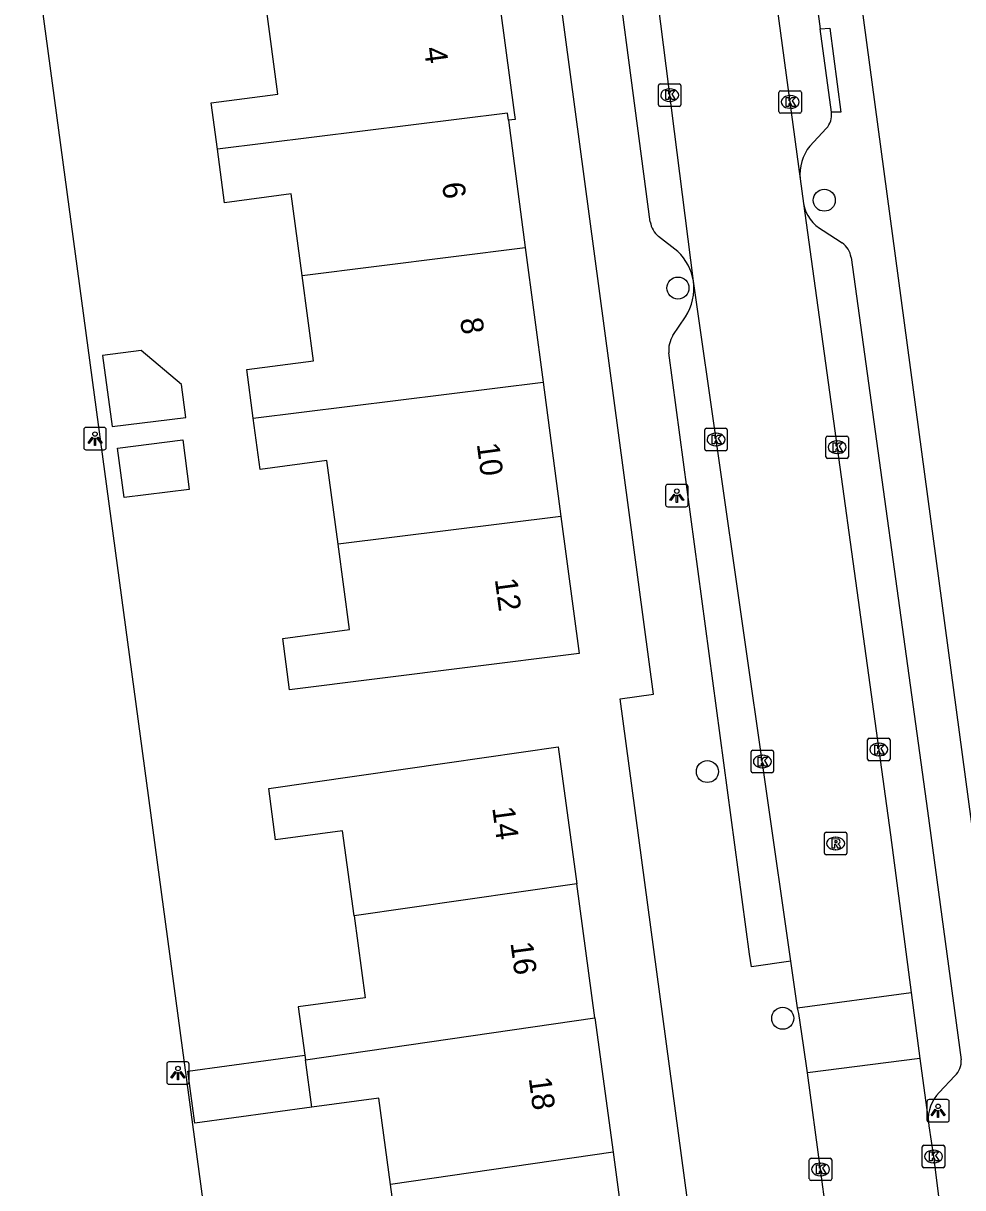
# Model space of a CAD drawing. Extents: x 163427 to 164190, y 380331 to 381641.
# Drawn here: x 163513.3 to 163555.1, y 381440.5 to 381492.3 of the extents above; entities that cross this region are included whole.
import ezdxf

# ---------------------------------------------------------------- set-up
doc = ezdxf.new("R2010")
doc.units = 0
for name, color, linetype in [('IMGEO_Boom', 7, 'Continuous'), ('IMGEO_Kolk', 7, 'Continuous'), ('IMGEO_Lichtpunt', 7, 'Continuous'), ('IMGEO_Pand', 7, 'Continuous'), ('IMGEO_Pand_nummerreeks', 7, 'Continuous'), ('IMGEO_Rijbaan_lokaal_open', 7, 'Continuous'), ('IMGEO_Rioolput', 7, 'Continuous'), ('IMGEO_Voetpad_open', 7, 'Continuous')]:
    doc.layers.add(name, color=color, linetype=linetype)

msp = doc.modelspace()

# ---------------------------------------------------------------- linework, layer by layer
at = {"layer": 'IMGEO_Boom'}
for centre in [(163548.902, 381484.415), (163542.391, 381480.505), (163543.702, 381458.979), (163547.053, 381447.995)]:
    msp.add_circle(centre, 0.489, dxfattribs=at)
at = {"layer": 'IMGEO_Kolk'}
for p, q in [((163541.6, 381489.594), (163542.452, 381489.594)), ((163541.525, 381488.668), (163541.525, 381489.52)), ((163542.013, 381489.374), (163542.038, 381489.374)), ((163542.526, 381489.52), (163542.526, 381488.668)), ((163546.887, 381488.365), (163546.887, 381489.217)), ((163546.962, 381489.291), (163547.814, 381489.291)), ((163547.375, 381489.071), (163547.4, 381489.071)), ((163547.888, 381489.217), (163547.888, 381488.365)), ((163542.452, 381488.594), (163541.6, 381488.594)), ((163542.036, 381488.814), (163542.011, 381488.814)), ((163547.814, 381488.291), (163546.962, 381488.291)), ((163547.398, 381488.511), (163547.373, 381488.511)), ((163543.587, 381473.337), (163543.587, 381474.189)), ((163543.662, 381474.263), (163544.514, 381474.263)), ((163544.075, 381474.043), (163544.1, 381474.043)), ((163544.588, 381474.189), (163544.588, 381473.337)), ((163548.975, 381472.992), (163548.975, 381473.844)), ((163549.05, 381473.918), (163549.902, 381473.918)), ((163549.463, 381473.698), (163549.488, 381473.698)), ((163549.976, 381473.844), (163549.976, 381472.992)), ((163544.514, 381473.263), (163543.662, 381473.263)), ((163544.098, 381473.483), (163544.073, 381473.483)), ((163549.486, 381473.138), (163549.461, 381473.138)), ((163549.902, 381472.918), (163549.05, 381472.918)), ((163550.827, 381459.533), (163550.827, 381460.385)), ((163550.902, 381460.459), (163551.754, 381460.459)), ((163551.315, 381460.239), (163551.34, 381460.239)), ((163551.828, 381460.385), (163551.828, 381459.533)), ((163545.648, 381459), (163545.648, 381459.852)), ((163545.723, 381459.926), (163546.575, 381459.926)), ((163546.136, 381459.706), (163546.161, 381459.706)), ((163546.649, 381459.852), (163546.649, 381459)), ((163551.338, 381459.679), (163551.313, 381459.679)), ((163546.159, 381459.146), (163546.134, 381459.146)), ((163551.754, 381459.459), (163550.902, 381459.459)), ((163546.575, 381458.926), (163545.723, 381458.926)), ((163553.265, 381441.417), (163553.265, 381442.269)), ((163553.34, 381442.343), (163554.192, 381442.343)), ((163553.753, 381442.123), (163553.778, 381442.123)), ((163554.266, 381442.269), (163554.266, 381441.417)), ((163548.238, 381440.841), (163548.238, 381441.693)), ((163548.313, 381441.767), (163549.165, 381441.767)), ((163548.726, 381441.547), (163548.751, 381441.547)), ((163549.239, 381441.693), (163549.239, 381440.841)), ((163553.776, 381441.563), (163553.751, 381441.563)), ((163548.749, 381440.987), (163548.724, 381440.987)), ((163554.192, 381441.343), (163553.34, 381441.343)), ((163549.165, 381440.767), (163548.313, 381440.767))]:
    msp.add_line(p, q, dxfattribs=at)
for points in [[(163541.6, 381489.594), (163542.452, 381489.594)], [(163541.525, 381488.668), (163541.525, 381489.52)], [(163541.846, 381489.294), (163541.969, 381489.294), (163541.969, 381489.143), (163542.099, 381489.294), (163542.263, 381489.294), (163542.117, 381489.143), (163542.27, 381488.894), (163542.118, 381488.894), (163542.033, 381489.058), (163541.969, 381488.991), (163541.969, 381488.894), (163541.846, 381488.894), (163541.846, 381489.294)], [(163542.526, 381489.52), (163542.526, 381488.668)], [(163546.887, 381488.365), (163546.887, 381489.217)], [(163546.962, 381489.291), (163547.814, 381489.291)], [(163547.888, 381489.217), (163547.888, 381488.365)], [(163542.452, 381488.594), (163541.6, 381488.594)], [(163547.208, 381488.991), (163547.331, 381488.991), (163547.331, 381488.84), (163547.461, 381488.991), (163547.625, 381488.991), (163547.479, 381488.84), (163547.632, 381488.591), (163547.48, 381488.591), (163547.395, 381488.755), (163547.331, 381488.688), (163547.331, 381488.591), (163547.208, 381488.591), (163547.208, 381488.991)], [(163547.814, 381488.291), (163546.962, 381488.291)], [(163543.587, 381473.337), (163543.587, 381474.189)], [(163543.662, 381474.263), (163544.514, 381474.263)], [(163544.588, 381474.189), (163544.588, 381473.337)], [(163543.908, 381473.963), (163544.031, 381473.963), (163544.031, 381473.812), (163544.161, 381473.963), (163544.325, 381473.963), (163544.179, 381473.812), (163544.332, 381473.563), (163544.18, 381473.563), (163544.095, 381473.727), (163544.031, 381473.66), (163544.031, 381473.563), (163543.908, 381473.563), (163543.908, 381473.963)], [(163548.975, 381472.992), (163548.975, 381473.844)], [(163549.05, 381473.918), (163549.902, 381473.918)], [(163549.296, 381473.618), (163549.419, 381473.618), (163549.419, 381473.467), (163549.549, 381473.618), (163549.713, 381473.618), (163549.567, 381473.467), (163549.72, 381473.218), (163549.568, 381473.218), (163549.483, 381473.382), (163549.419, 381473.315), (163549.419, 381473.218), (163549.296, 381473.218), (163549.296, 381473.618)], [(163549.976, 381473.844), (163549.976, 381472.992)], [(163544.514, 381473.263), (163543.662, 381473.263)], [(163549.902, 381472.918), (163549.05, 381472.918)], [(163550.827, 381459.533), (163550.827, 381460.385)], [(163550.902, 381460.459), (163551.754, 381460.459)], [(163551.148, 381460.159), (163551.271, 381460.159), (163551.271, 381460.008), (163551.401, 381460.159), (163551.565, 381460.159), (163551.419, 381460.008), (163551.572, 381459.759), (163551.42, 381459.759), (163551.335, 381459.923), (163551.271, 381459.856), (163551.271, 381459.759), (163551.148, 381459.759), (163551.148, 381460.159)], [(163551.828, 381460.385), (163551.828, 381459.533)], [(163545.648, 381459), (163545.648, 381459.852)], [(163545.723, 381459.926), (163546.575, 381459.926)], [(163545.969, 381459.626), (163546.092, 381459.626), (163546.092, 381459.475), (163546.222, 381459.626), (163546.386, 381459.626), (163546.24, 381459.475), (163546.393, 381459.226), (163546.241, 381459.226), (163546.156, 381459.39), (163546.092, 381459.323), (163546.092, 381459.226), (163545.969, 381459.226), (163545.969, 381459.626)], [(163546.649, 381459.852), (163546.649, 381459)], [(163551.754, 381459.459), (163550.902, 381459.459)], [(163546.575, 381458.926), (163545.723, 381458.926)], [(163553.265, 381441.417), (163553.265, 381442.269)], [(163553.34, 381442.343), (163554.192, 381442.343)], [(163553.586, 381442.043), (163553.709, 381442.043), (163553.709, 381441.892), (163553.839, 381442.043), (163554.003, 381442.043), (163553.857, 381441.892), (163554.01, 381441.643), (163553.858, 381441.643), (163553.773, 381441.807), (163553.709, 381441.74), (163553.709, 381441.643), (163553.586, 381441.643), (163553.586, 381442.043)], [(163554.266, 381442.269), (163554.266, 381441.417)], [(163548.238, 381440.841), (163548.238, 381441.693)], [(163548.313, 381441.767), (163549.165, 381441.767)], [(163548.559, 381441.467), (163548.682, 381441.467), (163548.682, 381441.316), (163548.812, 381441.467), (163548.976, 381441.467), (163548.83, 381441.316), (163548.983, 381441.067), (163548.831, 381441.067), (163548.746, 381441.231), (163548.682, 381441.164), (163548.682, 381441.067), (163548.559, 381441.067), (163548.559, 381441.467)], [(163549.239, 381441.693), (163549.239, 381440.841)], [(163554.192, 381441.343), (163553.34, 381441.343)], [(163549.165, 381440.767), (163548.313, 381440.767)]]:
    msp.add_lwpolyline(points, dxfattribs=at)
for centre, start, end in [((163541.602, 381489.518), 91.552, 178.448), ((163541.602, 381489.518), 91.552, 178.448), ((163542.45, 381489.518), 1.552, 88.448), ((163542.45, 381489.518), 1.552, 88.448), ((163546.964, 381489.215), 91.552, 178.448), ((163546.964, 381489.215), 91.552, 178.448), ((163547.812, 381489.215), 1.552, 88.448), ((163547.812, 381489.215), 1.552, 88.448), ((163541.602, 381488.67), 181.552, 268.448), ((163541.602, 381488.67), 181.552, 268.448), ((163542.45, 381488.67), 271.552, 358.448), ((163542.45, 381488.67), 271.552, 358.448), ((163546.964, 381488.367), 181.552, 268.448), ((163546.964, 381488.367), 181.552, 268.448), ((163547.812, 381488.367), 271.552, 358.448), ((163547.812, 381488.367), 271.552, 358.448), ((163543.664, 381474.187), 91.552, 178.448), ((163543.664, 381474.187), 91.552, 178.448), ((163544.512, 381474.187), 1.552, 88.448), ((163544.512, 381474.187), 1.552, 88.448), ((163549.052, 381473.842), 91.552, 178.448), ((163549.052, 381473.842), 91.552, 178.448), ((163549.9, 381473.842), 1.552, 88.448), ((163549.9, 381473.842), 1.552, 88.448), ((163543.664, 381473.339), 181.552, 268.448), ((163543.664, 381473.339), 181.552, 268.448), ((163544.512, 381473.339), 271.552, 358.448), ((163544.512, 381473.339), 271.552, 358.448), ((163549.052, 381472.994), 181.552, 268.448), ((163549.052, 381472.994), 181.552, 268.448), ((163549.9, 381472.994), 271.552, 358.448), ((163549.9, 381472.994), 271.552, 358.448), ((163550.904, 381460.383), 91.552, 178.448), ((163550.904, 381460.383), 91.552, 178.448), ((163551.752, 381460.383), 1.552, 88.448), ((163551.752, 381460.383), 1.552, 88.448), ((163545.725, 381459.85), 91.552, 178.448), ((163545.725, 381459.85), 91.552, 178.448), ((163546.573, 381459.85), 1.552, 88.448), ((163546.573, 381459.85), 1.552, 88.448), ((163550.904, 381459.535), 181.552, 268.448), ((163550.904, 381459.535), 181.552, 268.448), ((163551.752, 381459.535), 271.552, 358.448), ((163551.752, 381459.535), 271.552, 358.448), ((163545.725, 381459.002), 181.552, 268.448), ((163545.725, 381459.002), 181.552, 268.448), ((163546.573, 381459.002), 271.552, 358.448), ((163546.573, 381459.002), 271.552, 358.448), ((163553.342, 381442.267), 91.552, 178.448), ((163553.342, 381442.267), 91.552, 178.448), ((163554.19, 381442.267), 1.552, 88.448), ((163554.19, 381442.267), 1.552, 88.448), ((163548.315, 381441.691), 91.552, 178.448), ((163548.315, 381441.691), 91.552, 178.448), ((163549.163, 381441.691), 1.552, 88.448), ((163549.163, 381441.691), 1.552, 88.448), ((163553.342, 381441.419), 181.552, 268.448), ((163553.342, 381441.419), 181.552, 268.448), ((163554.19, 381441.419), 271.552, 358.448), ((163554.19, 381441.419), 271.552, 358.448), ((163548.315, 381440.843), 181.552, 268.448), ((163548.315, 381440.843), 181.552, 268.448), ((163549.163, 381440.843), 271.552, 358.448), ((163549.163, 381440.843), 271.552, 358.448)]:
    msp.add_arc(centre, 0.0765, start, end, dxfattribs=at)
for centre, major_axis, ratio, start_param, end_param in [((163542.012, 381489.094), (-0.387, 0.002), 0.722429, 4.712389, 7.853982), ((163542.037, 381489.094), (-0.39, 0.002), 0.717154, 1.570796, 4.712389), ((163547.374, 381488.791), (-0.387, 0.002), 0.722429, 4.712389, 7.853982), ((163547.399, 381488.791), (-0.39, 0.002), 0.717154, 1.570796, 4.712389), ((163544.074, 381473.763), (-0.387, 0.002), 0.722429, 4.712389, 7.853982), ((163544.099, 381473.763), (-0.39, 0.002), 0.717154, 1.570796, 4.712389), ((163549.462, 381473.418), (-0.387, 0.002), 0.722429, 4.712389, 7.853982), ((163549.487, 381473.418), (-0.39, 0.002), 0.717154, 1.570796, 4.712389), ((163551.314, 381459.959), (-0.387, 0.002), 0.722429, 4.712389, 7.853982), ((163551.339, 381459.959), (-0.39, 0.002), 0.717154, 1.570796, 4.712389), ((163546.135, 381459.426), (-0.387, 0.002), 0.722429, 4.712389, 7.853982), ((163546.16, 381459.426), (-0.39, 0.002), 0.717154, 1.570796, 4.712389), ((163553.752, 381441.843), (-0.387, 0.002), 0.722429, 4.712389, 7.853982), ((163553.777, 381441.843), (-0.39, 0.002), 0.717154, 1.570796, 4.712389), ((163548.725, 381441.267), (-0.387, 0.002), 0.722429, 4.712389, 7.853982), ((163548.75, 381441.267), (-0.39, 0.002), 0.717154, 1.570796, 4.712389)]:
    msp.add_ellipse(centre, major_axis=major_axis, ratio=ratio, start_param=start_param, end_param=end_param, dxfattribs=at)
at = {"layer": 'IMGEO_Lichtpunt'}
for p, q in [((163515.956, 381474.207), (163515.956, 381473.4)), ((163515.956, 381474.207), (163515.956, 381473.4)), ((163516.858, 381474.302), (163516.05, 381474.302)), ((163516.858, 381474.302), (163516.05, 381474.302)), ((163516.952, 381473.4), (163516.952, 381474.207)), ((163516.952, 381473.4), (163516.952, 381474.207)), ((163516.05, 381473.306), (163516.858, 381473.306)), ((163516.05, 381473.306), (163516.858, 381473.306)), ((163541.844, 381471.667), (163541.844, 381470.86)), ((163541.844, 381471.667), (163541.844, 381470.86)), ((163542.746, 381471.762), (163541.938, 381471.762)), ((163542.746, 381471.762), (163541.938, 381471.762)), ((163542.84, 381470.86), (163542.84, 381471.667)), ((163542.84, 381470.86), (163542.84, 381471.667)), ((163541.938, 381470.766), (163542.746, 381470.766)), ((163541.938, 381470.766), (163542.746, 381470.766)), ((163520.549, 381446.054), (163519.741, 381446.054)), ((163520.549, 381446.054), (163519.741, 381446.054)), ((163519.647, 381445.959), (163519.647, 381445.152)), ((163519.647, 381445.959), (163519.647, 381445.152)), ((163520.643, 381445.152), (163520.643, 381445.959)), ((163520.643, 381445.152), (163520.643, 381445.959)), ((163519.741, 381445.058), (163520.549, 381445.058)), ((163519.741, 381445.058), (163520.549, 381445.058)), ((163553.469, 381444.28), (163553.469, 381443.473)), ((163553.469, 381444.28), (163553.469, 381443.473)), ((163554.371, 381444.375), (163553.563, 381444.375)), ((163554.371, 381444.375), (163553.563, 381444.375)), ((163554.465, 381443.473), (163554.465, 381444.28)), ((163554.465, 381443.473), (163554.465, 381444.28)), ((163553.563, 381443.379), (163554.371, 381443.379)), ((163553.563, 381443.379), (163554.371, 381443.379))]:
    msp.add_line(p, q, dxfattribs=at)
for points in [[(163516.33, 381473.871), (163516.369, 381473.843), (163516.181, 381473.581), (163516.143, 381473.608), (163516.33, 381473.871)], [(163516.432, 381473.823), (163516.479, 381473.823), (163516.479, 381473.501), (163516.432, 381473.501), (163516.432, 381473.823)], [(163516.542, 381473.843), (163516.58, 381473.87), (163516.767, 381473.608), (163516.728, 381473.58), (163516.542, 381473.843)], [(163542.218, 381471.331), (163542.257, 381471.303), (163542.069, 381471.041), (163542.031, 381471.068), (163542.218, 381471.331)], [(163542.32, 381471.283), (163542.367, 381471.283), (163542.367, 381470.961), (163542.32, 381470.961), (163542.32, 381471.283)], [(163542.43, 381471.303), (163542.468, 381471.33), (163542.655, 381471.068), (163542.616, 381471.04), (163542.43, 381471.303)], [(163520.021, 381445.623), (163520.06, 381445.595), (163519.872, 381445.333), (163519.834, 381445.36), (163520.021, 381445.623)], [(163520.123, 381445.575), (163520.17, 381445.575), (163520.17, 381445.253), (163520.123, 381445.253), (163520.123, 381445.575)], [(163520.233, 381445.595), (163520.271, 381445.622), (163520.458, 381445.36), (163520.419, 381445.332), (163520.233, 381445.595)], [(163553.843, 381443.944), (163553.882, 381443.916), (163553.694, 381443.654), (163553.656, 381443.681), (163553.843, 381443.944)], [(163553.945, 381443.896), (163553.992, 381443.896), (163553.992, 381443.574), (163553.945, 381443.574), (163553.945, 381443.896)], [(163554.055, 381443.916), (163554.093, 381443.943), (163554.28, 381443.681), (163554.241, 381443.653), (163554.055, 381443.916)]]:
    msp.add_lwpolyline(points, dxfattribs=at)
for centre in [(163516.455, 381474.005), (163542.343, 381471.465), (163520.146, 381445.757), (163553.968, 381444.078)]:
    msp.add_circle(centre, 0.0994, dxfattribs=at)
for centre, start, end in [((163516.05, 381474.207), 90, 180), ((163516.05, 381474.207), 90, 180), ((163516.858, 381474.207), 0, 90), ((163516.858, 381474.207), 0, 90), ((163516.05, 381473.4), 180, 270), ((163516.05, 381473.4), 180, 270), ((163516.858, 381473.4), 270, 0), ((163516.858, 381473.4), 270, 360), ((163541.938, 381471.667), 90, 180), ((163541.938, 381471.667), 90, 180), ((163542.746, 381471.667), 0, 90), ((163542.746, 381471.667), 0, 90), ((163541.938, 381470.86), 180, 270), ((163541.938, 381470.86), 180, 270), ((163542.746, 381470.86), 270, 0), ((163542.746, 381470.86), 270, 360), ((163519.741, 381445.959), 90, 180), ((163519.741, 381445.959), 90, 180), ((163520.549, 381445.959), 0, 90), ((163520.549, 381445.959), 0, 90), ((163519.741, 381445.152), 180, 270), ((163519.741, 381445.152), 180, 270), ((163520.549, 381445.152), 270, 0), ((163520.549, 381445.152), 270, 360), ((163553.563, 381444.28), 90, 180), ((163553.563, 381444.28), 90, 180), ((163554.371, 381444.28), 0, 90), ((163554.371, 381444.28), 0, 90), ((163553.563, 381443.473), 180, 270), ((163553.563, 381443.473), 180, 270), ((163554.371, 381443.473), 270, 0), ((163554.371, 381443.473), 270, 360)]:
    msp.add_arc(centre, 0.0946, start, end, dxfattribs=at)
at = {"layer": 'IMGEO_Pand'}
for points in [[(163533.968, 381494.509), (163534.274, 381494.551), (163534.306, 381494.31), (163535.105, 381488.326), (163535.148, 381488.003), (163534.846, 381487.974)], [(163521.901, 381486.681), (163521.625, 381488.748), (163524.595, 381489.143), (163524.076, 381493.035)], [(163534.846, 381487.974), (163534.804, 381488.288), (163521.901, 381486.681)], [(163534.846, 381487.974), (163535.597, 381482.304)], [(163525.673, 381481.067), (163525.188, 381484.701), (163522.219, 381484.305), (163521.901, 381486.681)], [(163525.673, 381481.067), (163535.597, 381482.304)], [(163535.597, 381482.304), (163536.39, 381476.319)], [(163523.497, 381474.713), (163523.209, 381476.873), (163526.179, 381477.268), (163525.673, 381481.067)], [(163516.789, 381477.502), (163517.211, 381474.335), (163520.503, 381474.745), (163520.308, 381476.207), (163518.51, 381477.731), (163516.789, 381477.502)], [(163523.497, 381474.713), (163536.39, 381476.319)], [(163536.39, 381476.319), (163537.183, 381470.334)], [(163527.268, 381469.099), (163526.772, 381472.826), (163523.802, 381472.43), (163523.497, 381474.713)], [(163517.455, 381473.384), (163520.355, 381473.745), (163520.65, 381471.539), (163517.749, 381471.177), (163517.455, 381473.384)], [(163537.183, 381470.334), (163537.992, 381464.23), (163533.031, 381463.612), (163525.109, 381462.624), (163524.805, 381464.91), (163527.773, 381465.304), (163527.268, 381469.099)], [(163537.183, 381470.334), (163527.268, 381469.099)], [(163527.98, 381452.555), (163527.466, 381456.342), (163524.492, 381455.938), (163524.182, 381458.219), (163532.122, 381459.367), (163537.07, 381460.082), (163537.893, 381453.985)], [(163537.893, 381453.985), (163527.98, 381452.555)], [(163538.7, 381448.009), (163537.893, 381453.985)], [(163527.98, 381452.555), (163528.476, 381448.905), (163525.5, 381448.499), (163525.792, 381446.35)], [(163525.819, 381446.15), (163538.7, 381448.009)], [(163538.7, 381448.009), (163539.507, 381442.033)], [(163526.106, 381444.037), (163520.901, 381443.332), (163520.587, 381445.644), (163525.792, 381446.35)], [(163525.792, 381446.35), (163525.819, 381446.15)], [(163526.106, 381444.037), (163525.819, 381446.15)], [(163529.601, 381440.603), (163529.08, 381444.44), (163526.106, 381444.037)], [(163539.507, 381442.033), (163529.601, 381440.603)], [(163539.507, 381442.033), (163540.271, 381436.372)], [(163527.44, 381434.199), (163527.116, 381436.588), (163530.091, 381436.993), (163529.601, 381440.603)]]:
    msp.add_lwpolyline(points, dxfattribs=at)
at = {"layer": 'IMGEO_Rijbaan_lokaal_open'}
for points in [[(163542.971, 381521.306), (163545.852, 381500), (163547.83, 381485.368)], [(163543.08, 381480.808), (163540.658, 381500), (163538.748, 381515.131)], [(163523.981, 381419.703), (163513.264, 381499.338)], [(163547.83, 381485.368), (163547.979, 381484.273)], [(163547.979, 381484.273), (163551.848, 381456.16), (163552.773, 381449.148)], [(163547.416, 381450.538), (163543.08, 381480.808)], [(163547.714, 381448.459), (163547.416, 381450.538)], [(163547.714, 381448.459), (163552.773, 381449.148)], [(163552.773, 381449.148), (163553.162, 381446.201)], [(163548.151, 381445.563), (163547.973, 381446.804), (163547.772, 381448.204), (163547.744, 381448.327), (163547.714, 381448.459)], [(163553.162, 381446.201), (163548.151, 381445.563)], [(163553.162, 381446.201), (163553.536, 381443.371)], [(163548.986, 381439.398), (163548.736, 381441.267), (163548.151, 381445.563)], [(163553.536, 381443.371), (163553.557, 381443.21), (163553.761, 381441.842), (163553.981, 381440.08)]]:
    msp.add_lwpolyline(points, dxfattribs=at)
at = {"layer": 'IMGEO_Rioolput'}
for p, q in [((163548.909, 381455.352), (163548.909, 381456.204)), ((163548.984, 381456.278), (163549.836, 381456.278)), ((163549.397, 381456.058), (163549.422, 381456.058)), ((163549.91, 381456.204), (163549.91, 381455.352)), ((163549.42, 381455.498), (163549.395, 381455.498)), ((163549.836, 381455.278), (163548.984, 381455.278))]:
    msp.add_line(p, q, dxfattribs=at)
for points in [[(163548.909, 381455.352), (163548.909, 381456.204)], [(163548.984, 381456.278), (163549.836, 381456.278)], [(163549.498, 381455.976), (163549.246, 381455.978), (163549.246, 381455.578)], [(163549.424, 381455.897), (163549.37, 381455.897), (163549.37, 381455.816)], [(163549.91, 381456.204), (163549.91, 381455.352)], [(163549.246, 381455.578), (163549.37, 381455.578), (163549.37, 381455.74), (163549.381, 381455.74)], [(163549.37, 381455.816), (163549.422, 381455.816)], [(163549.428, 381455.711), (163549.499, 381455.578), (163549.639, 381455.578), (163549.574, 381455.704)], [(163549.836, 381455.278), (163548.984, 381455.278)]]:
    msp.add_lwpolyline(points, dxfattribs=at)
for centre, radius, start, end in [((163548.986, 381456.202), 0.0765, 91.552, 178.448), ((163548.986, 381456.202), 0.0765, 91.552, 178.448), ((163549.43, 381455.801), 0.0964, 77.0061, 93.1865), ((163549.444, 381455.858), 0.0378, 276.6634, 79.6772), ((163549.497, 381455.866), 0.109, 350.3612, 89.416), ((163549.834, 381456.202), 0.0765, 1.552, 88.448), ((163549.834, 381456.202), 0.0765, 1.552, 88.448), ((163549.38, 381455.687), 0.0533, 26.0293, 88.6989), ((163549.406, 381456.005), 0.19, 274.7715, 282.9687), ((163549.495, 381455.866), 0.112, 277.5842, 350.9817), ((163549.479, 381455.651), 0.108, 29.5134, 73.7905), ((163548.986, 381455.354), 0.0765, 181.552, 268.448), ((163548.986, 381455.354), 0.0765, 181.552, 268.448), ((163549.834, 381455.354), 0.0765, 271.552, 358.448), ((163549.834, 381455.354), 0.0765, 271.552, 358.448)]:
    msp.add_arc(centre, radius, start, end, dxfattribs=at)
for centre, major_axis, ratio, start_param, end_param in [((163549.396, 381455.778), (-0.387, 0.002), 0.722429, 4.712389, 7.853982), ((163549.421, 381455.778), (-0.39, 0.002), 0.717154, 1.570796, 4.712389)]:
    msp.add_ellipse(centre, major_axis=major_axis, ratio=ratio, start_param=start_param, end_param=end_param, dxfattribs=at)
at = {"layer": 'IMGEO_Voetpad_open'}
for points in [[(163556.995, 381445.271), (163550.532, 381493.434), (163549.67, 381494.227), (163548.887, 381500), (163545.916, 381521.903)], [(163545.129, 381518.832), (163547.658, 381500), (163548.727, 381492.039)], [(163541.163, 381483.452), (163538.982, 381500), (163537.364, 381512.278)], [(163545.149, 381422.545), (163539.823, 381462.212), (163541.312, 381462.422), (163536.277, 381500), (163535.961, 381502.355), (163535.005, 381502.264)], [(163548.727, 381492.039), (163549.144, 381492.08), (163549.638, 381488.335), (163549.225, 381488.332)], [(163549.225, 381488.332), (163548.727, 381492.039)], [(163548.992, 381487.606), (163548.263, 381486.824)], [(163548.854, 381483.073), (163549.695, 381482.511)], [(163542.383, 381482.127), (163541.53, 381482.804)], [(163550.094, 381481.871), (163553.497, 381457.225), (163554.995, 381446.148)], [(163542.17, 381478.391), (163542.723, 381479.23)], [(163547.416, 381450.538), (163545.661, 381450.286), (163545.579, 381450.857), (163541.994, 381477.616)], [(163554.715, 381445.435), (163554.012, 381444.698)]]:
    msp.add_lwpolyline(points, dxfattribs=at)
for centre, radius, start, end in [((163548.321, 381488.222), 0.911, 317.4577, 6.9557), ((163549.769, 381485.584), 1.951, 140.5252, 186.3509), ((163549.592, 381484.53), 1.633, 189.0479, 243.1487), ((163542.151, 381483.584), 0.997, 187.6006, 231.4502), ((163549.183, 381481.747), 0.92, 7.7306, 56.1513), ((163540.855, 381480.476), 2.25, 8.4886, 47.218), ((163540.788, 381480.497), 2.313, 326.784, 7.7205), ((163543.121, 381477.768), 1.137, 146.7503, 187.6603), ((163554.122, 381446.079), 0.876, 312.6217, 4.4977), ((163555.231, 381443.512), 1.701, 135.7848, 184.749)]:
    msp.add_arc(centre, radius, start, end, dxfattribs=at)

# ---------------------------------------------------------------- texts
at = {"layer": 'IMGEO_Pand_nummerreeks'}
for s, rotation, p in [('4', 277.5915, (163531.089, 381491.188)), ('6', 277.5915, (163531.892, 381485.162)), ('8', 277.5939, (163532.696, 381479.131)), ('10', 277.5939, (163533.438, 381473.562)), ('12', 277.5939, (163534.241, 381467.541)), ('14', 277.6778, (163534.126, 381457.365)), ('16', 277.6774, (163534.937, 381451.349)), ('18', 277.6778, (163535.749, 381445.33))]:
    msp.add_text(s, height=1, rotation=rotation, dxfattribs=at).set_placement(p)

doc.saveas('drawing.dxf')
